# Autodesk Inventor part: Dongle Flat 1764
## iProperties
Created: 2010-01
Part Number: Dongle Flat 1764
Document SubType Name: Modeling
Designer: jgehrig
Density: 1 g/cm^3
Author: jgehrig
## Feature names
1. Extrusion1
